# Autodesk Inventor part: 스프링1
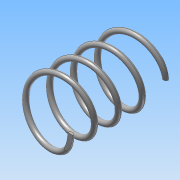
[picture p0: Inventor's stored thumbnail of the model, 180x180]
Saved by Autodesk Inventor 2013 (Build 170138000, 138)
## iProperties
Created: 2014-11
Part Number: 스프링1
Material: 강철, 연강
Document SubType Name: Modeling
Designer: Administrator
Density: 7.86 g/cm^3
Mass: 2.84316 g
Surface Area: 9.78737 cm^2
Volume: 0.361725 cm^3
Author: Administrator
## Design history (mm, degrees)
sketch "스케치1"
  geometry: L1 (0, 0)-(0, 27.999); L2 (0, 27.999)-(8.25, 27.999); L3 (0, 0)-(8.25, 0); C1 r 0.75 at (8.25, 0)
  constraints: 6 end point, 1 centre point, 1 coincident, 1 parallel, 1 perpendicular, 1 vertical
  dimensions: "d0" = 27.99924 distance of L1.start L1.end (derived); "d1" = 8.25 distance of L1.end L2.end; "d2" = 8.25 distance of L1.start L3.end; "d4" = 1.5 diameter of C1
feature "코일1" sketch "스케치1" pitch "d5" = 10; turns "d7" = 4; dims "d6" = 27.99924 (= d0), "d8" = 0, angle "d9" = 90 deg, angle "d10" = 90 deg, "d11" = 0, "d12" = 0
sketch "스케치2"
  geometry: L1 (0, 10)-(27.999, 10); L2 (27.999, 10)-(27.999, -10); L3 (27.999, -10)-(0, -10); L4 (0, -10)-(0, 10); 2 further points
  constraints: 8 end point, 2 parallel, 1 coincident, 1 horizontal, 1 midpoint, 1 perpendicular
  dimensions: "d13" = 27.99924 distance of L1.start L1.end (derived); "d15" = 20 distance of L1.end L2.end
extrude "돌출1" sketch "스케치2" stored distance "d16" = 10; taper "d17" = 0 deg
node "솔리드1"
